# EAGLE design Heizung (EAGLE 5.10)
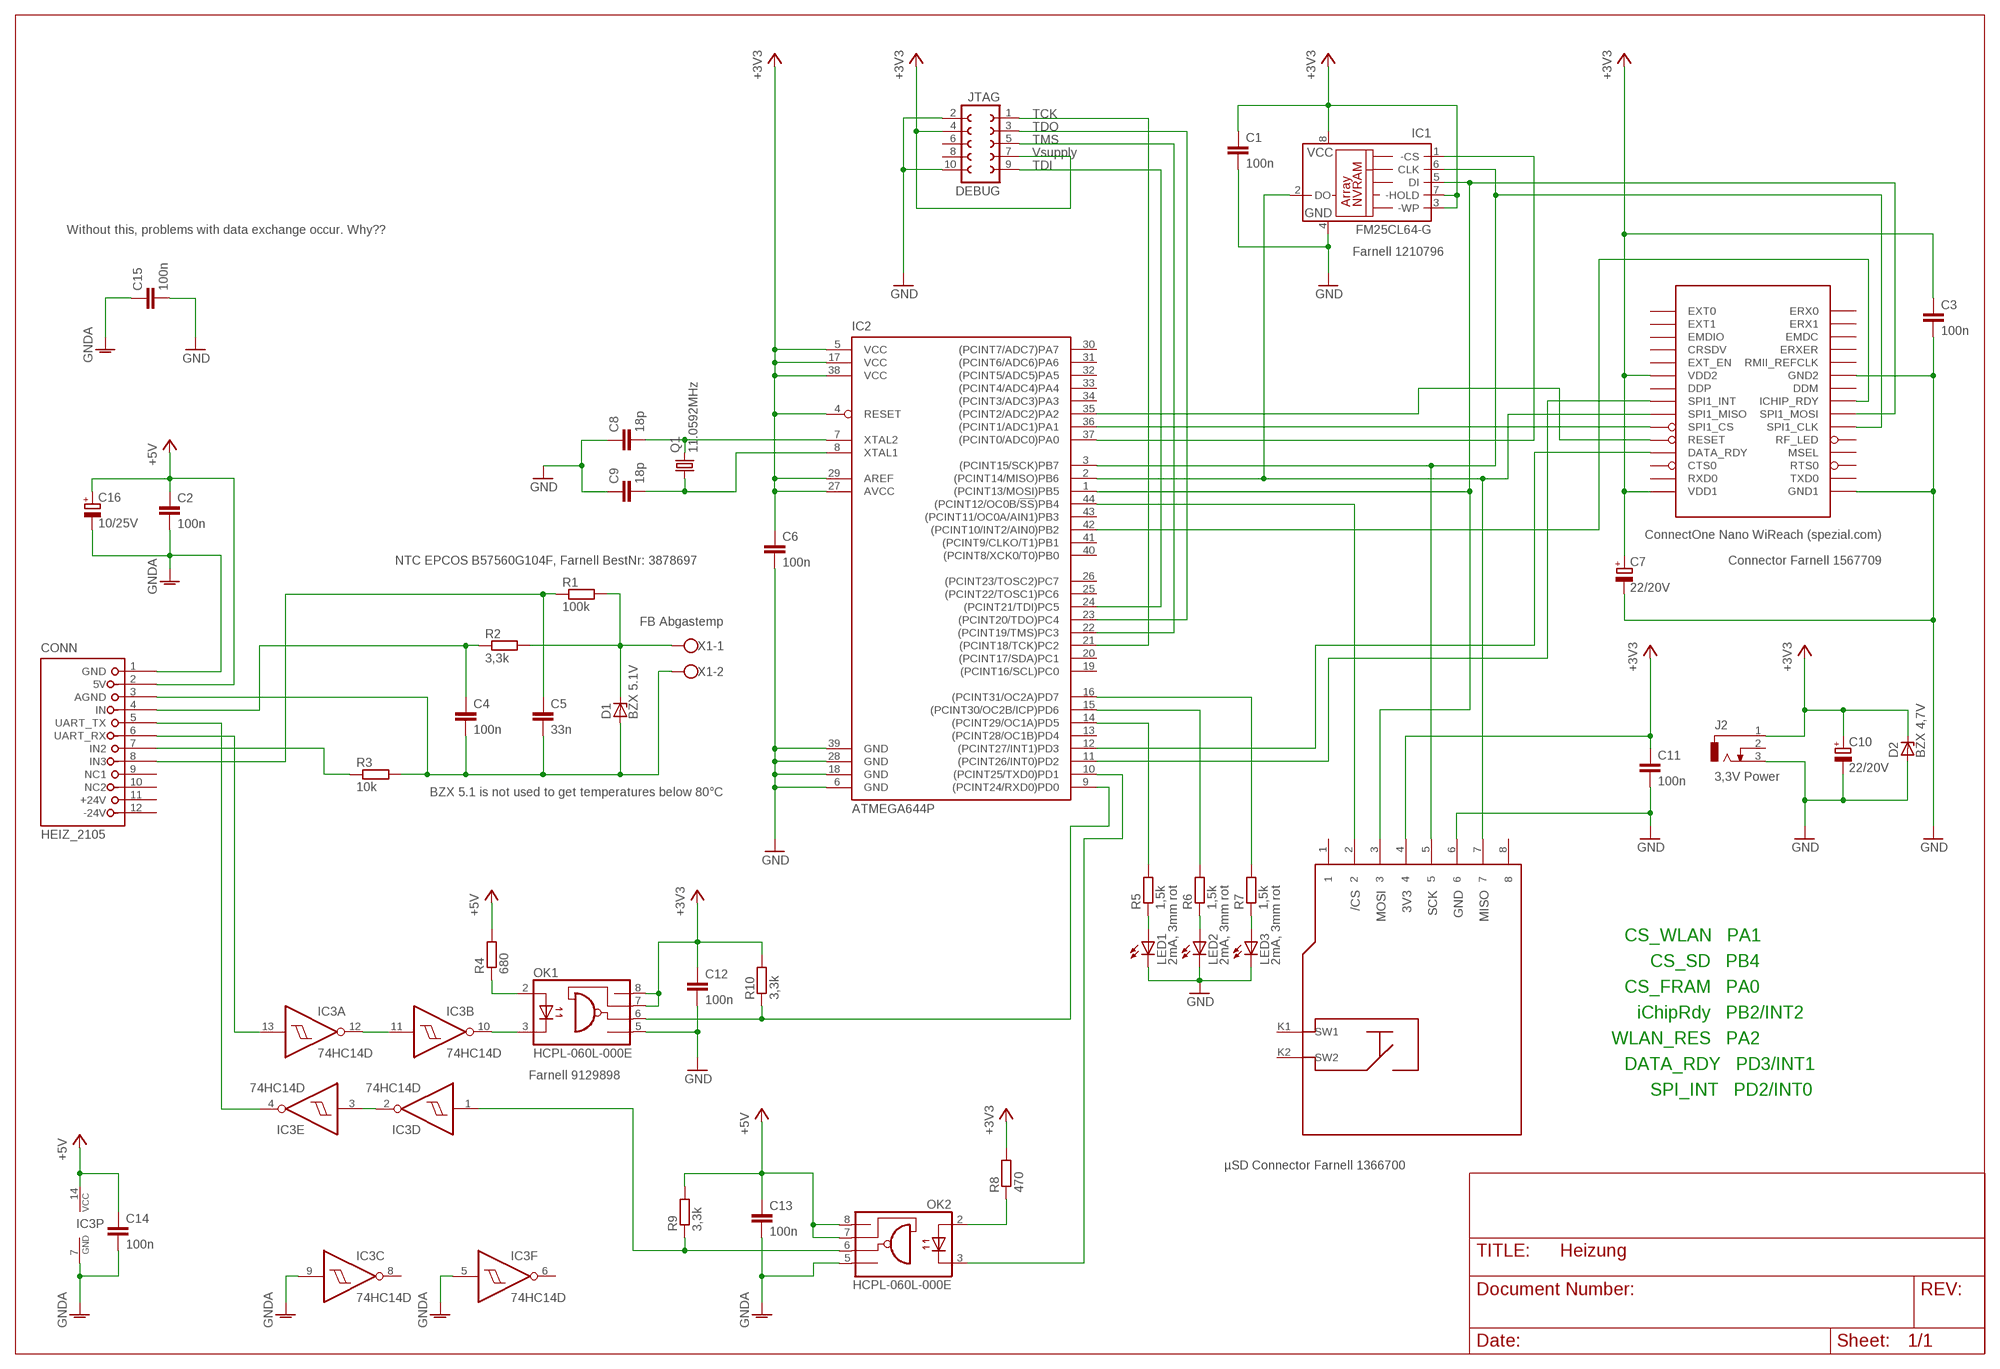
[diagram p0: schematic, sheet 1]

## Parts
C1  100n  C-EUC1206  [C1206]
C2  100n  C-EUC1206  [C1206]
C3  100n  C-EUC1206  [C1206]
C4  100n  C-EUC1206  [C1206]
C5  33n  C-EUC0805K  [C0805K]
C6  100n  C-EUC1206  [C1206]
C7  22/20V  CPOL-EUD/7343-31W  [D/7343-31W]
C8  18p  C-EUC0805K  [C0805K]
C9  18p  C-EUC0805K  [C0805K]
C10  22/20V  CPOL-EUD/7343-31W  [D/7343-31W]
C11  100n  C-EUC1206  [C1206]
C12  100n  C-EUC1206  [C1206]
C13  100n  C-EUC1206  [C1206]
C14  100n  C-EUC1206  [C1206]
C15  100n  C-EUC1206  [C1206]
C16  10/25V  CPOL-EUD/7343-31W  [D/7343-31W]
CONN  HEIZ_2105  [2105HEIZ]
D1  BZX 5.1V  ZENER-DIODEZD-10  [ZDIO-10]
D2  BZX 4,7V  ZENER-DIODEZD-10  [ZDIO-10]
DEBUG  JTAG  FE05-2  [FE05-2]
IC1  FM25CL64-G  FM25-S  [SO8]
IC2  ATMEGA644P  ATMEGA644A  [TQFP44]
IC3  74HC14D  [SO14]
J2  3,3V Power  DCJ0303  [DCJ0303]
LED1  2mA, 3mm rot  LED3MM  [LED3MM]
LED2  2mA, 3mm rot  LED3MM  [LED3MM]
LED3  2mA, 3mm rot  LED3MM  [LED3MM]
OK1  HCPL-060L-000E  HCPL0600  [SOIC08]
OK2  HCPL-060L-000E  HCPL0600  [SOIC08]
Q1  11.0592MHz  CRYSTALHC49UP  [HC49UP]
R1  100k  R-EU_M0805  [M0805]
R2  3,3k  R-EU_M0805  [M0805]
R3  10k  R-EU_M1206  [M1206]
R4  680  R-EU_M0805  [M0805]
R5  1,5k  R-EU_M0805  [M0805]
R6  1,5k  R-EU_M0805  [M0805]
R7  1,5k  R-EU_M0805  [M0805]
R8  470  R-EU_M0805  [M0805]
R9  3,3k  R-EU_M0805  [M0805]
R10  3,3k  R-EU_M0805  [M0805]
U$1  NANOWIBREAKOUT  [MOLEX2]
X1  FB Abgastemp  W237-102  [W237-102]
X2  MICRO-SD  [MICRO-SD]

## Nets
+3V3: C1.1 C3.1 C6.1 C7.+ C10.+ C11.1 C12.1 D2.C DEBUG.4 DEBUG.7 IC1.3(-WP) IC1.7(-HOLD) IC1.8(VCC) IC2.4(RESET) IC2.5(VCC) IC2.17(VCC) IC2.27(AVCC) IC2.29(AREF) IC2.38(VCC) J2.1 OK1.7(VE) OK1.8(VCC) R8.2 R10.2 U$1.P1VDD(VDD1) U$1.PVDD2(VDD2) X2.4
+5V: C2.1 C13.1 C14.1 C16.+ CONN.2(5V) IC3.14(P:VCC) OK2.7(VE) OK2.8(VCC) R4.2 R9.2
GND: C1.2 C3.2 C6.2 C7.- C8.1 C9.1 C10.- C11.2 C12.2 C15.2 D2.A DEBUG.2 DEBUG.10 IC1.4(GND) IC2.6(GND) IC2.18(GND) IC2.28(GND) IC2.39(GND) J2.3 LED1.K(C) LED2.K(C) LED3.K(C) OK1.5(GND) U$1.P2GND(GND2) U$1.PGND1(GND1) X2.6
GNDA: C2.2 C13.2 C14.2 C15.1 C16.- CONN.1(GND) IC3.5(F:I) IC3.7(P:GND) IC3.9(C:I) OK2.5(GND)
N$1: IC2.36((PCINT1/ADC1)PA1) U$1.PSPI_CS(SPI1_CS)
N$2: IC2.42((PCINT10/INT2/AIN0)PB2) U$1.PICHIP_RDY(ICHIP_RDY)
N$3: IC2.44((PCINT12/OC0B/!SS!)PB4) X2.2
N$4: IC2.12((PCINT27/INT1)PD3) U$1.PDATA_RDY(DATA_RDY)
N$5: IC1.2(DO) IC2.2((PCINT14/MISO)PB6) U$1.PSPI_MISO(SPI1_MISO) X2.7
N$6: IC1.5(DI) IC2.1((PCINT13/MOSI)PB5) U$1.PMOSI(SPI1_MOSI) X2.3
N$7: DEBUG.1 IC2.21((PCINT18/TCK)PC2)
N$8: DEBUG.5 IC2.22((PCINT19/TMS)PC3)
N$9: DEBUG.9 IC2.24((PCINT21/TDI)PC5)
N$10: DEBUG.3 IC2.23((PCINT20/TDO)PC4)
N$11: IC1.1(-CS) IC2.37((PCINT0/ADC0)PA0)
N$12: IC1.6(CLK) IC2.3((PCINT15/SCK)PB7) U$1.PSPI_CLK(SPI1_CLK) X2.5
N$13: IC2.11((PCINT26/INT0)PD2) U$1.PSPI_INT(SPI1_INT)
N$14: IC2.35((PCINT2/ADC2)PA2) U$1.PRESET(RESET)
N$15: C9.2 IC2.8(XTAL1) Q1.1
N$16: IC2.9((PCINT24/RXD0)PD0) OK1.6(VO) R10.1
N$17: OK2.2(A) R8.1
N$18: IC2.10((PCINT25/TXD0)PD1) OK2.3(C)
N$19: IC3.11(B:I) IC3.12(A:O)
N$20: IC3.10(B:O) OK1.3(C)
N$21: OK1.2(A) R4.1
N$22: IC3.2(D:O) IC3.3(E:I)
N$23: IC3.1(D:I) OK2.6(VO) R9.1
N$24: CONN.6(UART_RX) IC3.13(A:I)
N$25: CONN.5(UART_TX) IC3.4(E:O)
N$26: C4.2 C5.2 CONN.3(AGND) D1.A R3.2 X1.2
N$27: D1.C R1.2 R2.2 X1.1
N$28: C5.1 CONN.8(IN3) R1.1
N$29: C4.1 CONN.4(IN) R2.1
N$30: IC2.16((PCINT31/OC2A)PD7) R7.2
N$31: C8.2 IC2.7(XTAL2) Q1.2
N$32: CONN.7(IN2) R3.1
N$33: IC2.15((PCINT30/OC2B/ICP)PD6) R6.2
N$34: IC2.14((PCINT29/OC1A)PD5) R5.2
N$35: LED1.A R5.1
N$36: LED2.A R6.1
N$37: LED3.A R7.1
Unconnected: CONN.9(NC1) CONN.10(NC2) DEBUG.6 DEBUG.8 IC2.13((PCINT28/OC1B)PD4) IC2.19((PCINT16/SCL)PC0) IC2.20((PCINT17/SDA)PC1) IC2.25((PCINT22/TOSC1)PC6) IC2.26((PCINT23/TOSC2)PC7) IC2.30((PCINT7/ADC7)PA7) IC2.31((PCINT6/ADC6)PA6) IC2.32((PCINT5/ADC5)PA5) IC2.33((PCINT4/ADC4)PA4) IC2.34((PCINT3/ADC3)PA3) IC2.40((PCINT8/XCK0/T0)PB0) IC2.41((PCINT9/CLKO/T1)PB1) IC2.43((PCINT11/OC0A/AIN1)PB3) IC3.6(F:O) IC3.8(C:O) J2.2 U$1.5CTS0(CTS0) U$1.6RTS0(RTS0) U$1.10RF_LED(RF_LED) U$1.17DDP(DDP) U$1.18DDM(DDM) U$1.21EXT_EN(EXT_EN) U$1.22RMII(RMII_REFCLK) U$1.23CRSDV(CRSDV) U$1.24ERXER(ERXER) U$1.25EMDIO(EMDIO) U$1.26EMDC(EMDC) U$1.27EXT1(EXT1) U$1.28ERX1(ERX1) U$1.29EXT0(EXT0) U$1.30ERX0(ERX0) U$1.P3RXD0(RXD0) U$1.P4TXD0(TXD0) U$1.PMSEL(MSEL) X2.1 X2.8 X2.K1(SW1) X2.K2(SW2)

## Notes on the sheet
- TCK
- TDO
- TMS
- Vsupply
- TDI
- Without this, problems with data exchange occur. Why??
- Farnell 1210796
- ConnectOne Nano WiReach (spezial.com)
- NTC EPCOS B57560G104F, Farnell BestNr: 3878697 | Connector Farnell 1567709
- BZX 5.1 is not used to get temperatures below 80°C
- CS_WLAN   PA1
- CS_SD   PB4
- CS_FRAM   PA0
- iChipRdy   PB2/INT2
- WLAN_RES   PA2
- Farnell 9129898 | DATA_RDY   PD3/INT1
- SPI_INT   PD2/INT0
- µSD Connector Farnell 1366700

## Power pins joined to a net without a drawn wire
+24V: CONN.11(+24V)
-24V: CONN.12(-24V)

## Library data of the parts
C1-C6 C8 C9 C11-C15 = rcl:C-EU: CAPACITOR, European symbol
C7 C10 C16 = rcl:CPOL-EU: POLARIZED CAPACITOR, European symbol
CONN = Michael:HEIZ_2105: Platinenlayout für KM271 Platine in Buderus Logamatic 2105 Steuerung
D1 D2 = diode:ZENER-DIODE: Z-Diode
DEBUG = con-lsta:FE05-2: FEMALE HEADER
IC1 = ramtron-2:FM25*: SPI Serial NVRAM
IC2 = atmel:ATMEGA644: 8-bit Microcontroller with 64K Bytes In-System Programmable Flash Source: http://www.atmel.com/dyn/resources/prod_documents/doc2593.pdf
IC3 = 74xx-eu:74*14: Hex schmitt trigger INVERTER
J2 = con-jack:DCJ0303: DC POWER JACK Source: DCJ0303.pdf
LED1-LED3 = led:LED: LED
OK1 OK2 = optocoupler:HCPL0600: HEWLETT PACKARD OPTO COUPLER
Q1 = crystal:CRYSTAL: CRYSTAL
R1-R10 = rcl:R-EU_: RESISTOR, European symbol
U$1 = Michael:NANOWI
X1 = con-wago-500:W237-102: WAGO SCREW CLAMP
X2 = welectronic:MICRO-SD

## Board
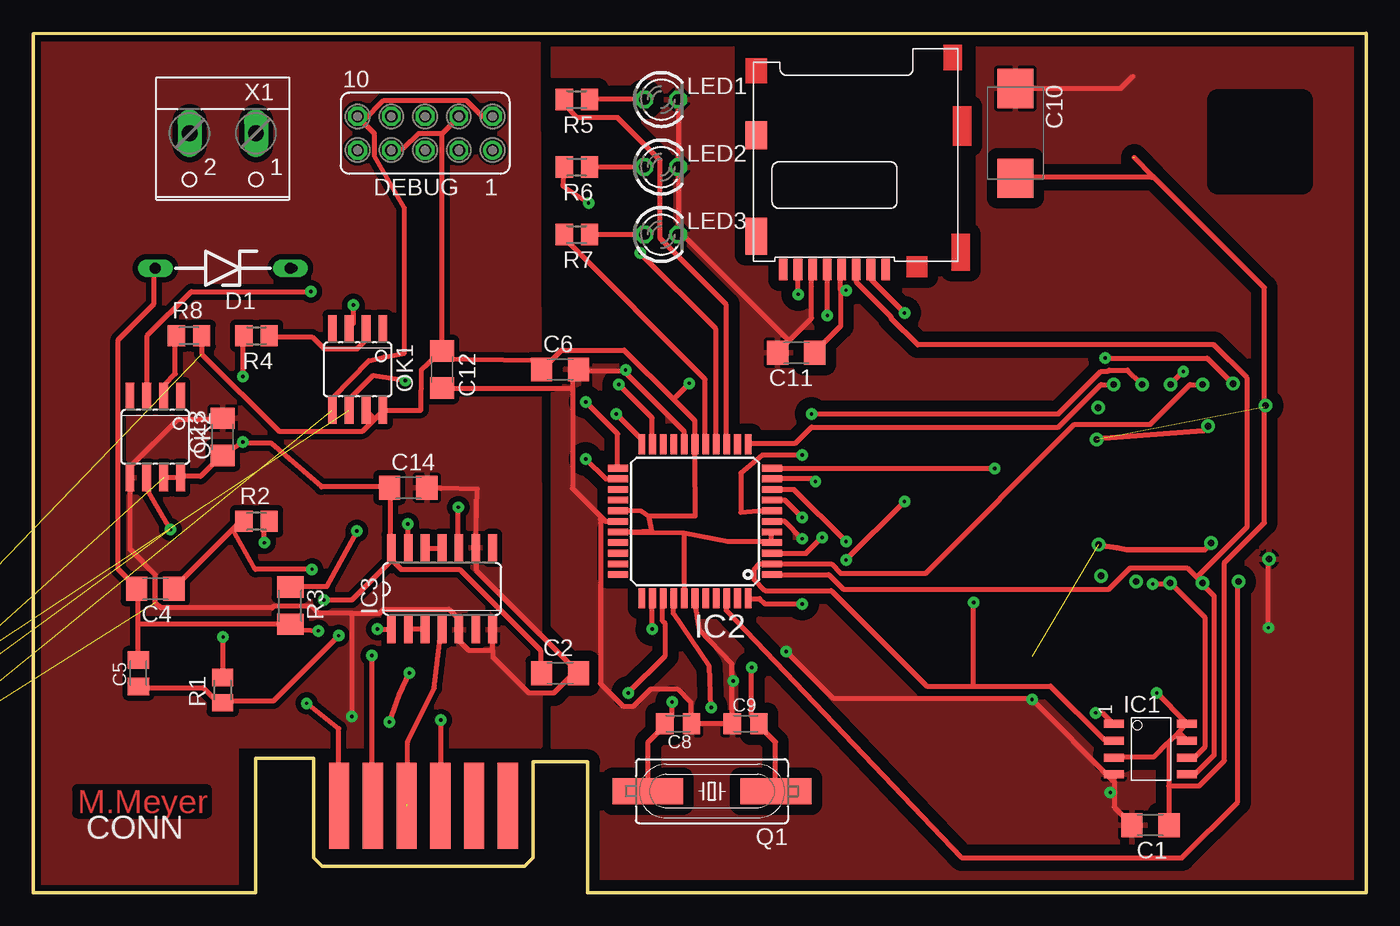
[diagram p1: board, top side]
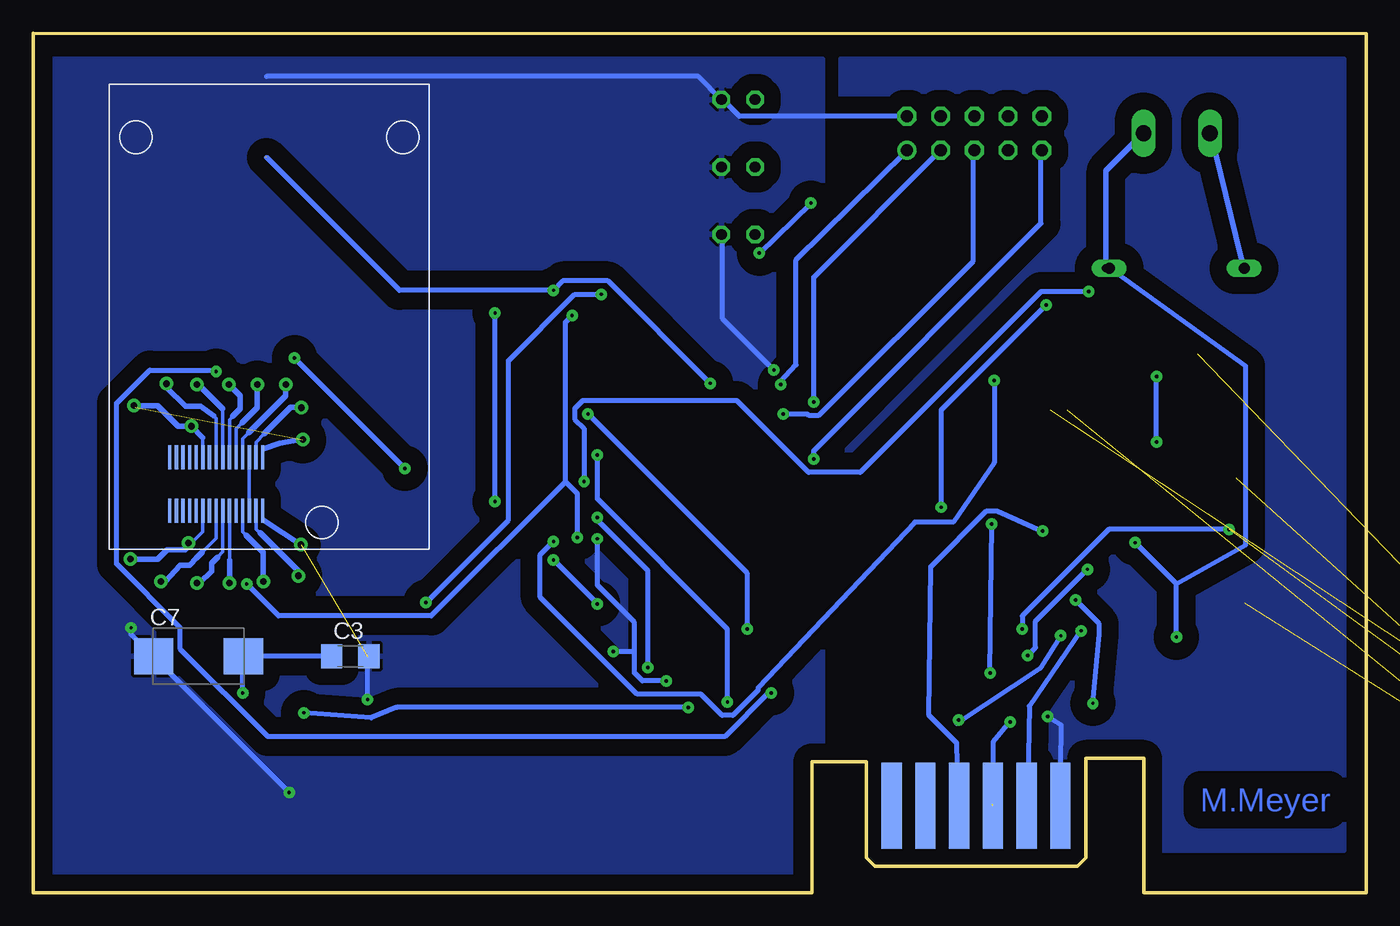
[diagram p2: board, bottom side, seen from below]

Size 100.38 x 64.69 mm. Coordinates in mm from the lower left corner, seen from the top.
Copper layers (1*16): Top 0.035mm / dielectric 1.5mm / Bottom 0.035mm
Design rules "Heizung": minimum track width 15mil, minimum drill 10mil, track to track 12mil, track to pad 12mil, pad to pad 12mil, via to via 12mil, smd to smd 12mil, copper to edge 18mil, drill to drill 12mil, minimum pad ring 10mil, minimum via ring 12mil, stop-mask expansion 4mil, vias tented up to drill 0mil, thermal gap 10mil
tRestrict: area 89.2,53.3 to 95.6,59.7; area 53.6,48.3 to 70.2,64.8
vRestrict: area 42.2,20.3 to 57.5,35.6; area 23.2,53.3 to 35.9,61; area 21.9,36.8 to 27,41.9; area 25.7,20.3 to 35.9,25.4; area 5.4,31.8 to 13,36.8; area 81.6,7.6 to 87.9,12.7; area 85.4,16.5 to 90.5,20.3; area 77.8,47 to 89.2,63.5; area 72.7,54.6 to 75.2,59.7; area 9.2,52.1 to 20.6,62.2; area 10.5,45.7 to 18.1,48.3; area 20.6,8.9 to 37.1,12.7

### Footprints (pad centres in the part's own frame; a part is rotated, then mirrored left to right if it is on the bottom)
C1206 = smd 1.6 x 1.8: 1 -1.4,0; 2 1.4,0
C0805K = smd 1.3 x 1.6: 1 -1,0; 2 1,0
D/7343-31W = smd 2.95 x 2.7: + 3.375,0; - -3.375,0
2105HEIZ = smd 1.524 x 6.477 bottom: 1 -77.6,6.54; 3 -75.06,6.54; 5 -72.52,6.54; 7 -69.98,6.54; 9 -67.44,6.54; 11 -64.9,6.54 | smd 1.524 x 6.477: 2 -77.6,6.54; 4 -75.06,6.54; 6 -72.52,6.54; 8 -69.98,6.54; 10 -67.44,6.54; 12 -64.9,6.54
ZDIO-10 = drill 0.813 long: A 5.08,0; C -5.08,0
FE05-2 = drill 0.914 round: 1 -5.08,1.27 | drill 0.914 octagon: 2 -5.08,-1.27; 3 -2.54,1.27; 4 -2.54,-1.27; 5 0,1.27; 6 0,-1.27; 7 2.54,1.27; 8 2.54,-1.27; 9 5.08,1.27; 10 5.08,-1.27
SO8 = smd 0.61 x 1.524: 1 -1.27,-2.743; 2 0,-2.743; 3 1.27,-2.743; 4 2.54,-2.743; 5 2.54,2.743; 6 1.27,2.743; 7 0,2.743; 8 -1.27,2.743
TQFP44 = smd 1.5 x 0.5: 1 -5.8,4; 2 -5.8,3.2; 3 -5.8,2.4; 4 -5.8,1.6; 5 -5.8,0.8; 6 -5.8,0; 7 -5.8,-0.8; 8 -5.8,-1.6; 9 -5.8,-2.4; 10 -5.8,-3.2; 11 -5.8,-4; 23 5.8,-4; 24 5.8,-3.2; 25 5.8,-2.4; 26 5.8,-1.6; 27 5.8,-0.8; 28 5.8,0; 29 5.8,0.8; 30 5.8,1.6; 31 5.8,2.4; 32 5.8,3.2; 33 5.8,4 | smd 0.5 x 1.5: 12 -4,-5.8; 13 -3.2,-5.8; 14 -2.4,-5.8; 15 -1.6,-5.8; 16 -0.8,-5.8; 17 0,-5.8; 18 0.8,-5.8; 19 1.6,-5.8; 20 2.4,-5.8; 21 3.2,-5.8; 22 4,-5.8; 34 4,5.8; 35 3.2,5.8; 36 2.4,5.8; 37 1.6,5.8; 38 0.8,5.8; 39 0,5.8; 40 -0.8,5.8; 41 -1.6,5.8; 42 -2.4,5.8; 43 -3.2,5.8; 44 -4,5.8
SO14 = smd 0.66 x 2.032: 1 -3.81,-3.073; 2 -2.54,-3.073; 3 -1.27,-3.073; 4 0,-3.073; 5 1.27,-3.073; 6 2.54,-3.073; 7 3.81,-3.073; 8 3.81,3.073; 9 2.54,3.073; 10 1.27,3.073; 11 0,3.073; 12 -1.27,3.073; 13 -2.54,3.073; 14 -3.81,3.073
DCJ0303 = drill 1 pad 2 long: 1 0,3.1; 2 4.8,0; 3 0,-3
LED3MM = drill 0.813 octagon: A -1.27,0; K 1.27,0
SOIC08 = smd 0.66 x 2.032: 1 -1.905,-3.073; 2 -0.635,-3.073; 3 0.635,-3.073; 4 1.905,-3.073; 5 1.905,3.073; 6 0.635,3.073; 7 -0.635,3.073; 8 -1.905,3.073
HC49UP = smd 5.334 x 1.93: 1 -4.826,0; 2 4.826,0
M0805 = smd 1.3 x 1.6: 1 -0.95,0; 2 0.95,0
M1206 = smd 1.6 x 2: 1 -1.4,0; 2 1.4,0
MOLEX2 = smd 1.8 x 0.25: 1VDD 11.7,-0.25; 2GND 15.7,-0.25; 3RXD0 11.7,-0.75; 4TXD0 15.7,-0.75; 5CTS0 11.7,-1.25; 6RTS0 15.7,-1.25; 7DATA_RDY 11.7,-1.75; 8MSEL 15.7,-1.75; 9RESET 11.7,-2.25; 10RF_LED 15.7,-2.25; 11SPI1_CS 11.7,-2.75; 12SPI1_CLK 15.7,-2.75; 13SPI1_MISO 11.7,-3.25; 14SPI1_MOSI 15.7,-3.25; 15SPI1_INT 11.7,-3.75; 16READYNESS 15.7,-3.75; 17DDP 11.7,-4.25; 18DDM 15.7,-4.25; 19VDD1 11.7,-4.75; 20GND1 15.7,-4.75; 21EXT_EN 11.7,-5.25; 22RMII 15.7,-5.25; 23CRSDV 11.7,-5.75; 24ERXER 15.7,-5.75; 25EMDIO 11.7,-6.25; 26EMDC 15.7,-6.25; 27EXT1 11.7,-6.75; 28ERX1 15.7,-6.75; 29EXT0 11.7,-7.25; 30ERX0 15.7,-7.25 | drill 0.5 pad 1.016 round: P1VDD 10.36,2.77; P2GND 18.27,2.64; P3RXD0 7.96,2.68; P4TXD0 20.61,2.45; P$1 9.35,-5.6; P$2 18.15,-5.85; PDATA_RDY 6.2,1.5; PGND1 19.35,-10.2; PICHIP_RDY 21.05,-7.9; PMOSI 21.15,-5.2; PMSEL 21.05,-0.2; PRESET 6.2,-0.65; PSPI_CLK 21.15,-2.75; PSPI_CS 6.2,-2.8; PSPI_INT 6.15,-7.5; PSPI_MISO 6.2,-5.2; PVDD2 7.8,-9.95
W237-102 = drill 1.194 long: 1 -2.5,-1.27; 2 2.5,-1.27
MICRO-SD = smd 0.65 x 1.6: 1 -10.54,16.6; 2 -9.44,16.6; 3 -8.34,16.6; 4 -7.24,16.6; 5 -6.14,16.6; 6 -5.04,16.6; 7 -3.94,16.6; 8 -2.84,16.6 | smd 1.6 x 2.1: K1 -0.8,6.5 | smd 1.6 x 2.8: K2 -0.8,14.1

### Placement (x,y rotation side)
C1  84.12,5.09 180 top
C2  39.67,16.52 0 top
C3  76.5,17.79 0 bottom
C4  9.19,22.87 180 top
C5  7.92,16.52 90 top
C6  39.67,39.38 0 top
C7  87.93,17.79 0 bottom
C8  48.56,12.71 180 top
C9  53.64,12.71 0 top
C10  73.96,57.16 270 top
C11  57.45,40.65 180 top
C12  30.78,39.38 270 top
C13  14.27,34.3 90 top
C14  28.24,30.49 0 top
C15  not placed on the board
C16  not placed on the board
CONN  100.63,0.01 0 top
D1  14.27,47 180 top
D2  not placed on the board
DEBUG  29.51,57.16 180 top
IC1  84.12,11.44 270 top
IC2  49.83,27.95 180 top
IC3  30.78,22.87 0 top
J2  not placed on the board
LED1  47.29,59.7 0 top
LED2  47.29,54.62 0 top
LED3  47.29,49.54 0 top
OK1  24.43,39.38 180 top
OK2  9.19,34.3 180 top
Q1  51.1,7.63 180 top
R1  14.27,15.25 90 top
R2  16.81,27.95 0 top
R3  19.35,21.6 270 top
R4  16.81,41.92 180 top
R5  40.94,59.7 180 top
R6  40.94,54.62 180 top
R7  40.94,49.54 180 top
R8  11.73,41.92 0 top
R9  not placed on the board
R10  not placed on the board
U$1  82.85,44.46 270 bottom
X1  14.27,55.89 180 top
X2  53.64,63.51 180 top

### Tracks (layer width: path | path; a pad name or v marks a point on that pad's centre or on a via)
+3V3  (via drill 0.25)  (5 unrouted)
  Top 0.381: IC2.5 55.6,27.14 55.6,26.44 IC2.4 55.4,26.44 52.3,26.44 49,27.07 | 45,27.14 44.1,27.14 IC2.29 | 45,27.14 46.57,27.18 46.32,28.34 | 46.32,28.34 45.81,28.69 45,28.74 44.1,28.74 IC2.27 | 49,27.07 49,22.24 IC2.38 | 45,27.14 49,27.07 | 46.32,28.34 49.85,28.34 49.8,32.74 49.8,33.74 IC2.17 49.8,33.94 49.8,35.54 48.2,37.14 | 30.8,57.14 29,57.14 27.8,55.94 27,55.94 DEBUG.7 | 30.8,57.14 32,58.34 DEBUG.4 | 25.7,35.64 26.3,36.24 OK1.8 29.2,36.31 29.25,39.41 | 25.7,35.64 24.8,34.74 18.5,34.74 12.7,40.54 12.7,41.84 R8.2 | 29.25,39.41 30.7,40.74 C12.1 30.8,40.94 30.8,57.14 | 29.25,39.41 30.11,40.2 38.07,40.07 C6.1 38.4,39.44 39.8,40.84 44.5,40.84 48.2,37.14 | OK1.7 25.1,36.24 25.7,35.64 | 86.25,12.09 86.8,12.64 IC1.8 86.8,12.84 v84.6,15.04 | 85.4,11.24 86.25,12.09 | 85.4,11.24 84.4,10.24 81.4,10.24 IC1.3 | IC1.7 86.8,11.54 86.25,12.09 | 85.5,8.04 85.5,11.14 85.4,11.24 | 85.5,8.04 85.5,5.14 C1.1 | 60.8,45.34 60.8,42.64 58.9,40.74 C11.1 | 60.8,45.34 60.8,46.84 X2.4 | 84.3,53.94 82.9,55.34 | 84.3,53.94 92.7,45.54 92.7,36.74 U$1.PVDD2 92.7,36.54 92.7,27.84 89.7,24.84 89.7,9.94 87.8,8.04 85.5,8.04 | C10.+ 74,53.84 84.2,53.84 84.3,53.94 | v61.2,45.34 60.8,45.34 | 48.2,37.14 v49.4,38.34
  Bottom 0.381: C3.1 78,17.84 84.5,17.84 C7.+ 84.6,17.64 v84.6,15.04 | 82.8,55.34 72.8,45.34 v61.2,45.34 60.5,46.04 57.1,46.04 v49.4,38.34
+5V  (via drill 0.25)  (2 unrouted)
  Top 0.381: OK2.7 9.9,31.24 11,31.24 OK2.8 11.2,31.34 12.6,31.34 14.1,32.84 C13.1 14.3,32.94 v15.8,33.93 15.9,33.83 17.9,33.83 21.7,30.54 26.7,30.54 C14.1 26.9,30.44 26.9,26.04 IC3.14 | v15.8,38.84 15.8,41.84 R4.2 | C2.1 38.2,16.54 38.2,18.24 32.1,24.34 27.7,24.34 27,25.04 27,25.94 IC3.14 | v20.59,14.25 23,12.35 CONN.2 | v21.9,22.04 24,22.04 26.9,24.94 IC3.14
  Bottom 0.381: v15.8,33.93 v15.8,38.84 | v20.59,14.25 20.1,19.44 20.1,20.24 v21.9,22.04
GND  (via drill 0.25)  (5 unrouted)
  Top 0.381: OK1.5 22.6,36.34 22.6,37.24 25.29,40.05 26.39,40.3 27.96,40.6 27.96,51.52 25.7,55.44 25.7,57.14 24.5,58.34 DEBUG.10 24.9,58.14 26.4,59.64 32.6,59.64 33.8,58.44 34.5,58.44 DEBUG.2 | 82.8,61.44 81.9,60.54 74,60.54 C10.- | 56.9,41.54 56.1,40.74 C11.2 | 56.9,41.54 58.6,43.24 58.6,46.84 X2.6 | LED1.K 48.6,59.64 48.6,54.74 LED2.K 48.6,54.54 48.6,49.64 LED3.K 48.8,49.64 56.9,41.54 | v93,19.94 93,25.04 U$1.PGND1 | 81.4,7.54 81.4,6.44 82.7,5.14 C1.2 | 81.4,8.44 81.4,7.54 | 81.4,8.44 81.4,8.84 IC1.4 | 81.4,8.44 81.3,8.44 v75.2,14.54 75.1,14.64 60.2,14.64 v56.7,18.14 | 81.4,7.54 v81.1,7.54 | 52.6,15.94 52.6,12.74 C9.1 52.5,12.74 49.6,12.74 C8.1 49.5,12.84 49.5,14.34 48.5,15.34 46.5,15.34 45.2,14.04 44.4,14.04 42.7,15.74 42.7,28.14 42.8,28.24 | 52.6,15.94 52.6,17.24 50.18,19.78 49.8,22.14 IC2.39 | v57.9,26.64 56.6,27.94 55.7,27.94 IC2.6 | 52.6,15.94 v52.7,15.94 | 42.8,28.24 40.6,30.44 40.6,37.94 | 42.8,28.24 43.1,27.94 44,27.94 IC2.28 | 40.6,37.94 40.6,38.94 41,39.34 C6.2 41.2,39.24 44.5,39.24 | 44.5,39.24 49,34.74 49,33.84 IC2.18 | C12.2 30.8,37.94 40.6,37.94 | v44.6,39.34 44.5,39.24
  Bottom 0.381: 82.8,61.44 50.3,61.44 LED1.K 48.4,59.64 47.2,58.44 DEBUG.2 | v93,19.94 93,19.44 91.4,17.84 C7.- 91.2,17.64 v81.1,7.54 | v75.2,14.54 75.2,17.74 C3.2 | v57.9,26.64 57.9,23.14 55.1,20.34 55.1,18.14 | 55.1,18.14 55.1,16.54 54.5,15.94 v52.7,15.94 | 55.1,18.14 v56.7,18.14 | v44.6,39.34 48.5,43.24 48.5,49.44 LED3.K
  pour Bottom (isolate 1.27): 40.94,62.75 99.11,62.75 99.11,1.02 40.94,1.02
  pour Top (isolate 0.813): 39.29,63.64 99.23,63.64 99.23,0.77 39.16,0.77 39.16,63.89
GNDA  (via drill 0.25)  (2 unrouted)
  Top 0.381: C13.2 14.2,35.64 10.9,35.64 7.3,32.04 OK2.5 7.3,31.04 7.3,25.84 9.2,23.94 9.2,21.84 9.6,21.44 18,21.44 18.1,21.54 21,21.54 21.5,21.04 24,21.04 | C14.2 29.7,30.44 30.7,30.44 33.43,30.38 33.3,26.04 IC3.9 33.4,25.84 33.4,24.24 41,16.64 C2.2 41,16.44 40.6,16.44 39.2,15.04 37.3,15.04 34.6,17.74 34.6,18.24 | 34.6,18.24 34.6,19.74 IC3.7 | 34.6,18.24 32.8,18.24 32.1,18.94 32.1,19.74 IC3.5 32,19.94 32,20.64 31.3,21.34 26.4,21.34 26.1,21.04 24,21.04 | v24,13.25 24,21.04
  Bottom 0.381: v24,13.25 v23.99,13.24 22.97,12.61 CONN.1
  pour Bottom (isolate 1.27): 1.7,62.75 39.54,62.75 39.54,3.18 1.7,3.18
  pour Top (isolate 0.406): 0.43,63.89 38.02,63.89 38.15,11.06 0.56,11.06
N$1  (via drill 0.25)
  Top 0.381: v44.8,15.04 47.6,17.84 47.6,20.24 47.4,20.44 47.4,22.14 IC2.36 | v86.6,39.24 85.7,38.34 U$1.PSPI_CS
  Bottom 0.381: v44.8,15.04 45,15.04 48.3,11.74 82.7,11.74 89.3,18.34 89.3,19.94 94.1,24.74 94.1,36.84 91.6,39.34 86.7,39.34 v86.6,39.24
N$2
  Top 0.381: IC2.42 52.2,22.14 52.2,21.24 69.93,2.62 86.5,2.62 90.7,6.82 90.7,23.34 U$1.PICHIP_RDY
N$3  (via drill 0.25)
  Top 0.381: v57.9,21.74 55.1,21.74 54.7,22.14 53.9,22.14 IC2.44 | v61.2,25.04 v65.6,29.44 | v65.6,43.64 63.1,46.14 63.1,46.84 X2.2
  Bottom 0.381: v57.9,21.74 v61.2,25.04 | v65.6,29.44 v65.6,43.64
N$4
  Top 0.381: IC2.12 53.9,33.84 57.4,33.84 58.6,35.04 77.2,35.04 80.4,38.24 81.3,38.24 U$1.PDATA_RDY
N$5  (via drill 0.25)
  Top 0.381: 70.8,15.54 76.6,15.54 80.6,11.54 81.3,11.54 IC1.2 | 70.8,15.54 67.3,15.54 60.1,22.74 55.1,22.74 54.3,23.54 54.3,24.34 54.7,24.74 55.6,24.74 IC2.2 55.8,24.74 60.1,24.74 60.8,24.04 67.2,24.04 78.4,35.24 84.1,35.24 87.1,38.24 88,38.24 U$1.PSPI_MISO | v57.6,45.04 57.6,46.84 X2.7 | 70.8,15.54 v70.8,21.84
  Bottom 0.381: v57.6,45.04 59.6,45.04 64.6,40.04 64.6,28.04 v70.8,21.84
N$6
  Top 0.381: 87.6,23.74 88,23.34 U$1.PMOSI 88.1,23.14 88.9,22.34 88.9,10.34 87.5,8.94 86.9,8.94 IC1.5 | 87.6,23.74 86.9,24.44 82.6,24.44 81,22.84 61,22.84 59.9,23.94 55.7,23.94 IC2.1 | X2.3 62,46.84 62,45.94 64.6,43.34 64.6,43.24 66.6,41.24 88.9,41.24 91.4,38.74 91.4,27.54 87.6,23.74
N$7  (via drill 0.25)
  Top 0.381: v44.1,38.24 46.6,35.74 46.6,33.84 IC2.21
  Bottom 0.381: v44.1,38.24 44.1,38.44 42.94,39.73 42.94,47.63 34.6,55.84 DEBUG.1
N$8  (via drill 0.25)
  Top 0.381: v43.9,36.04 45.8,34.14 45.8,33.84 IC2.22
  Bottom 0.381: v43.9,36.04 42.1,36.04 42,35.94 41.2,35.94 29.6,47.54 29.6,55.84 DEBUG.5
N$9  (via drill 0.25)
  Top 0.381: v41.6,32.64 43.1,31.14 44,31.14 IC2.24
  Bottom 0.381: v41.6,32.64 41.6,33.27 24.5,50.37 24.5,55.84 DEBUG.9
N$10  (via drill 0.25)
  Top 0.381: v41.6,36.94 44,34.54 44,32.04 IC2.23
  Bottom 0.381: v41.6,36.94 41.6,46.34 DEBUG.3
N$11  (via drill 0.25)
  Top 0.381: v51.05,13.94 50.92,17.03 48.2,21.02 48.2,22.14 IC2.37 | v80,13.54 80.5,13.54 81.3,12.74 IC1.1
  Bottom 0.381: v51.05,13.94 73,13.94 74.93,13.16 v80,13.54
N$12  (via drill 0.25)
  Top 0.381: IC1.6 86.9,10.24 87.5,10.24 88.2,10.94 88.2,20.74 85.7,23.24 U$1.PSPI_CLK 85.5,23.24 v84.3,23.24 | v59.4,26.74 58.2,25.54 55.7,25.54 IC2.3 | v59.8,43.44 59.8,46.84 X2.5
  Bottom 0.381: v59.4,26.74 59.4,30.04 60.3,30.94 | 60.3,30.94 60.3,42.94 v59.8,43.44 | v84.3,23.24 81.9,20.84 70.4,20.84 60.3,30.94
N$13  (via drill 0.25)
  Top 0.381: v72.4,31.94 55.7,31.94 IC2.11 | v80.7,40.24 88.4,40.24 90.3,38.34 U$1.PSPI_INT
  Bottom 0.381: v72.4,31.94 v80.7,40.24
N$14  (via drill 0.25)
  Top 0.381: v46.6,19.84 46.6,22.14 IC2.35 | v58.6,36.04 77.2,36.04 80.4,39.24 80.9,39.24 81,39.34 82.4,39.34 83.4,38.34 U$1.PRESET
  Bottom 0.381: v46.6,19.84 46.6,24.04 v58.6,36.04
N$15  (via drill 0.25)
  Top 0.381: v57.9,28.24 56.6,29.54 55.7,29.54 IC2.8 | v54.1,16.94 54.1,13.24 54.6,12.74 C9.2 54.7,12.54 55.9,11.34 55.9,7.64 Q1.1
  Bottom 0.381: v57.9,28.24 57.9,28.04 54.1,24.24 v54.1,16.94
N$16  (via drill 0.25)  (1 unrouted)
  Top 0.381: v61.2,26.44 57.3,30.34 55.7,30.34 IC2.9 | v28.01,38.56 25.6,38.94 23.8,37.14 23.8,36.34 OK1.6
  Bottom 0.381: v61.2,26.44 62.2,25.44 62.2,22.24 54.9,14.94 50.1,14.94 48.5,13.34 47.7,13.34 45.8,15.24 45.8,15.44 33.99,27.88 31.09,27.88 28.01,32.36 v28.01,38.56
N$17
  Top 0.381: R8.1 10.7,41.84 10.7,39.04 9.9,38.24 9.9,37.44 OK2.2
N$18  (via drill 0.25)
  Top 0.381: v58.9,30.94 58.7,31.14 55.7,31.14 IC2.10 | v20.91,45.24 11.9,45.24 8.6,41.94 8.6,37.44 OK2.3
  Bottom 0.381: v58.9,30.94 58.9,34.94 59.6,35.64 59.6,36.44 59,37.04 47.4,37.04 42,31.64 38.1,31.64 24.5,45.24 v20.91,45.24
N$19
  Top 0.381: IC3.12 29.6,25.94 30.7,25.94 IC3.11
N$20  (via drill 0.25)
  Top 0.381: v32,29.01 32,26.04 IC3.10 | v24.1,44.24 24.1,42.84 23.8,42.54 OK1.3
  Bottom 0.381: v32,29.01 32,36.34 v24.1,44.24
N$21
  Top 0.381: R4.1 17.8,41.84 21,41.84 21.9,40.94 24.4,40.94 25,41.54 25,42.44 OK1.2
N$22
  Top 0.381: IC3.2 28.3,19.84 29.5,19.84 IC3.3
N$23  (via drill 0.25)  (1 unrouted)
  Top 0.381: v10.33,27.34 8.6,30.34 8.6,31.14 OK2.6 | v25.9,19.84 26.9,19.84 IC3.1
  Bottom 0.381: v10.33,27.34 19.4,27.34 25.9,20.84 v25.9,19.84
N$24  (via drill 0.25)  (1 unrouted)
  Top 0.381: v28.2,27.74 28.2,26.04 IC3.13 | v28.33,16.54 27.57,14.87 v26.82,12.86
  Bottom 0.381: v28.33,16.54 v28.2,27.74 | v26.82,12.86 28.09,11.35 28.1,6.64
N$25  (1 unrouted)
  Top 0.381: 28.2,6.64 28.2,11.38 30.19,15.4 30.7,19.74 IC3.4
N$26  (via drill 0.25, 0.6)
  Top 0.381: 9.2,47.04 D1.A 9.1,46.84 9.1,44.33 6.4,41.63 6.4,24.34 7.7,23.04 C4.2 7.8,22.84 7.9,22.74 7.9,20.24 | v11.7,57.14 X1.2 | 7.9,20.24 7.9,17.54 C5.2 | 7.9,20.24 19.3,20.24 R3.2 19.5,20.14 19.8,19.84 v21.48,19.71
  Bottom 0.381: v21.48,19.71 25.37,14.04 25.5,6.64 CONN.3
  Bottom 0.406: v11.7,57.14 9.45,47.87 D1.A
N$27  (via drill 0.25, 0.6)
  Top 0.381: v14.3,19.24 14.3,16.24 R1.2 | v17.4,26.34 17.4,27.64 17.7,27.94 R2.2 | D1.C 19.3,47.04 | X1.1 16.8,57.14
  Top 0.406: 19.3,47.04 19.57,47.04 v19.61,47
  Bottom 0.381: v14.3,19.24 14.3,23.24 | 14.3,23.24 v17.4,26.34 | 14.3,23.24 9.08,26.18 9.08,39.63 19.05,46.81 D1.C
  Bottom 0.406: v19.61,47 19.61,54.32 X1.1
N$28  (via drill 0.25)
  Top 0.381: C5.1 8,15.44 12.8,15.44 13.9,14.34 14.2,14.34 R1.1 14.4,14.44 18.1,14.44 v23,19.34 | v30.69,12.98 30.69,7.76 30.7,6.64 CONN.8
  Bottom 0.381: v23,19.34 24.53,16.91 30.86,12.73 v30.69,12.98
N$29  (via drill 0.25)
  Top 0.381: 15,27.34 10.6,22.94 C4.1 | 15,27.34 15.6,27.94 15.8,27.94 R2.1 | v21,24.34 16.73,24.34 15,27.34 | v25.5,17.84 25.5,6.64 CONN.4
  Bottom 0.381: v21,24.34 24.9,20.44 24.9,18.44 v25.5,17.84
N$30
  Top 0.381: IC2.16 50.6,33.84 50.6,38.64 40,49.24 40,49.44 R7.2
N$31  (via drill 0.25)
  Top 0.381: v57.9,32.94 54.9,32.94 53.29,31.58 53.29,28.63 54.57,28.74 55.6,28.74 IC2.7 | v48.1,14.34 48.1,13.24 47.6,12.74 C8.2 47.5,12.54 46.3,11.34 46.3,7.64 Q1.2
  Bottom 0.381: v57.9,32.94 57.9,29.64 48.1,19.84 v48.1,14.34
N$32  (via drill 0.25)
  Top 0.381: v24.38,27.22 22.1,23.04 19.4,23.04 R3.1
  Bottom 0.381: v24.38,27.22 27.8,28.74 28.6,28.74 32.8,24.54 32.93,13.35 30.83,11.25 30.7,6.64 CONN.7
N$33  (via drill 0.25)
  Top 0.381: v45.7,48.14 51.4,42.44 51.4,33.84 IC2.15 | v41.82,51.89 39.91,53.16 40,54.34 40,54.54 R6.2
  Bottom 0.381: v45.7,48.14 v41.82,51.89
N$34
  Top 0.381: IC2.14 52.2,33.84 52.2,44.24 47.2,49.24 47.2,55.14 44,58.34 41,58.34 40,59.34 40,59.64 R5.2
N$35
  Top 0.381: R5.1 41.9,59.74 46,59.74 LED1.A
N$36
  Top 0.381: R6.1 41.9,54.64 46,54.64 LED2.A
N$37
  Top 0.381: R7.1 LED3.A
N$38
  pour Top (isolate 0.406): 0.94,11.31 15.29,11.31 15.29,0.64 0.68,0.64 0.81,11.18

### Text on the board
Top: M.Meyer
Bottom: M.Meyer
bRestrict: M.Meyer | M.Meyer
